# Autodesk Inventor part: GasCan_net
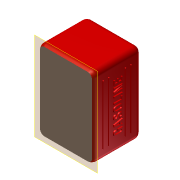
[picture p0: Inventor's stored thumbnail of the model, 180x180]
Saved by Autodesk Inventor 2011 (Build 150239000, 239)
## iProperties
Created: 2010-03
Part Number: GasCan_net
Document SubType Name: Modeling
Designer: boganb
Mass: 16963.2 g
Surface Area: 4155.97 cm^2
Volume: 16963.2 cm^3
Density: 1 g/cm^3
Author: boganb
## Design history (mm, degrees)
derived "Measured_Volume_P2.iam"
delete_face "Delete Face1"
body "Solid1"
node "Gas can.ipt:1"
sketch "GasCanVolume.ipt:1"
workplane "Work Plane1"
